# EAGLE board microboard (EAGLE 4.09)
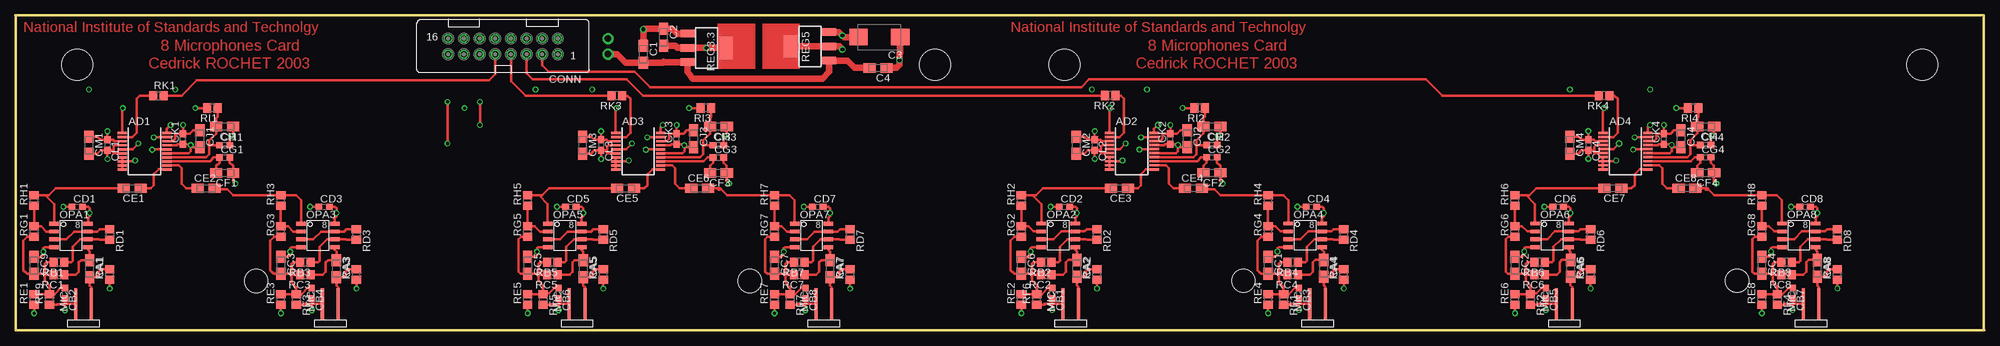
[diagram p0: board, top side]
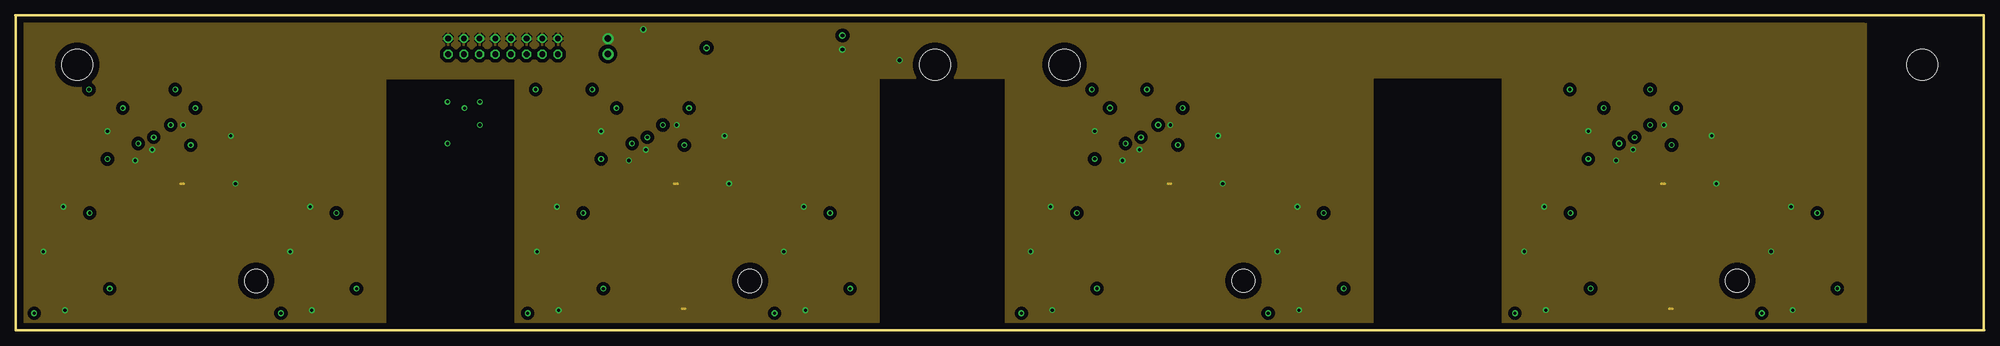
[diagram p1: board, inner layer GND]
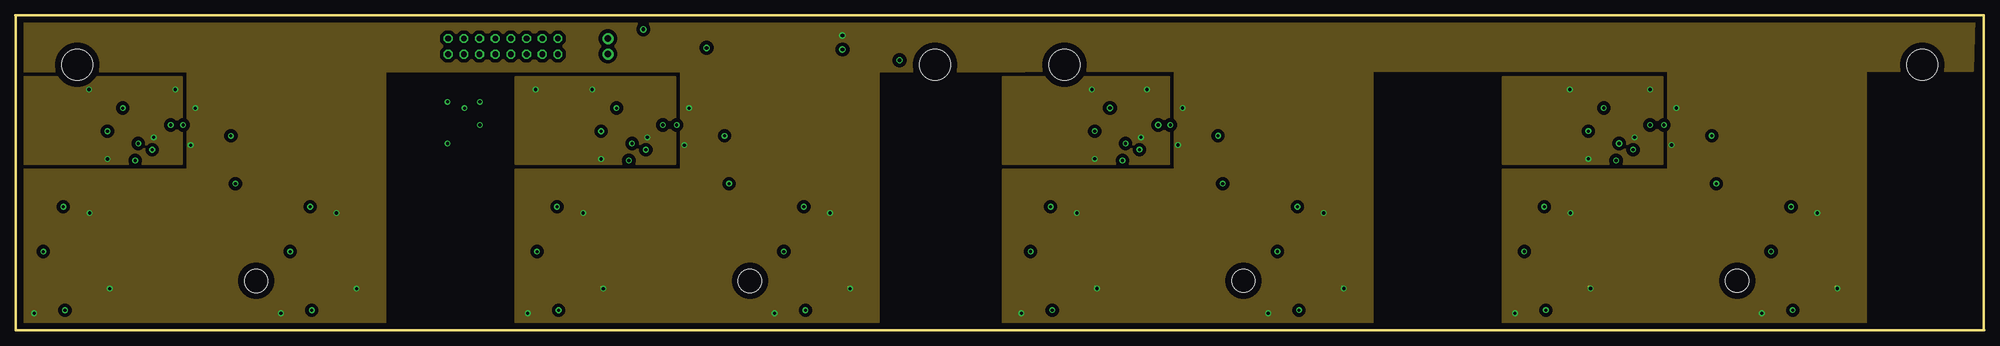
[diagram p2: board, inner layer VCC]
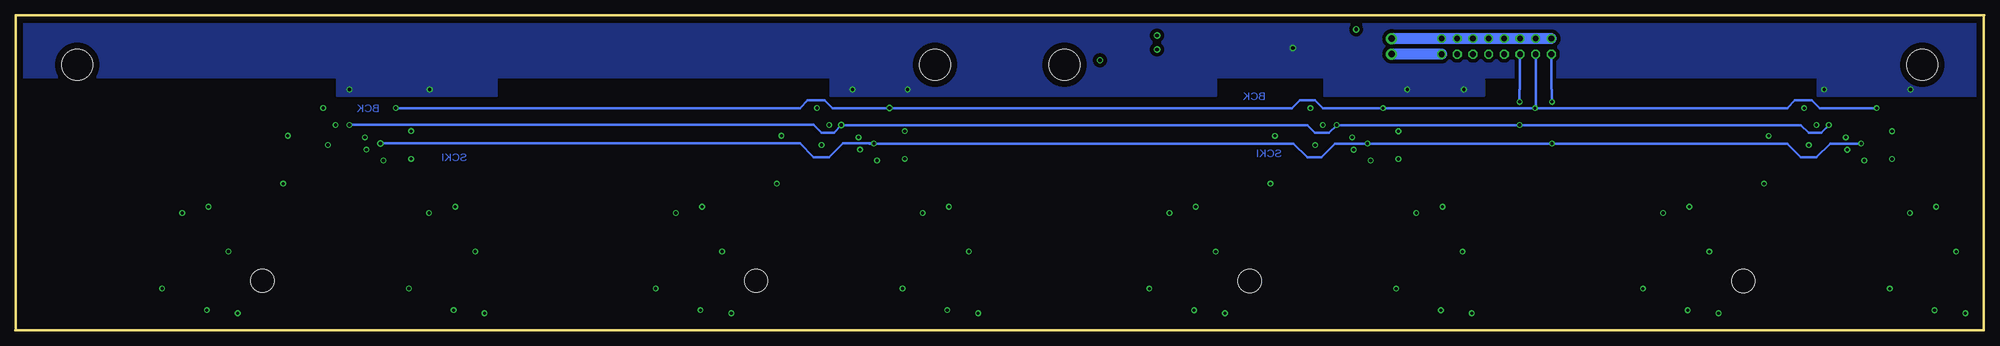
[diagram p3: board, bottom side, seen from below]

Size 319.04 x 51.01 mm. Coordinates in mm from the lower left corner, seen from the top.
Outline: 35.02,0 319.04,0
Outline: 0.02,51 0.02,0 35.02,0
Outline: 35.02,0 90.02,0
Outline: 35.02,0 60.02,0
Outline: 41.02,0 101.02,0
Outline: 319.02,0.01 319.02,51.01 0,51.01
Copper layers used: Top, GND, VCC, Bottom
Net classes: 0 default: width 0.305 mm, drill 0.203 mm, clearance 0.305 mm; 1 power: width 0.305 mm, drill 0.61 mm, clearance 0.61 mm
Holes 5.08 mm at 10.02,43 149.02,43 170.02,43.01 309.02,43.01
Holes 3.81 mm at 39.02,8 119.02,8 199.02,8.01 279.02,8.01

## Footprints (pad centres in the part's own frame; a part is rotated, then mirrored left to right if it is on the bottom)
SSOP20 = smd 0.4 x 1.5: 1 -2.925,-3.625; 2 -2.275,-3.625; 3 -1.625,-3.625; 4 -0.975,-3.625; 5 -0.325,-3.625; 6 0.325,-3.625; 7 0.975,-3.625; 8 1.625,-3.625; 9 2.275,-3.625; 10 2.925,-3.625; 11 2.925,3.625; 12 2.275,3.625; 13 1.625,3.625; 14 0.975,3.625; 15 0.325,3.625; 16 -0.325,3.625; 17 -0.975,3.625; 18 -1.625,3.625; 19 -2.275,3.625; 20 -2.925,3.625
A/3216-18R = smd 1.95 x 1.5: + 1.375,0; - -1.375,0
D/7343-31W = smd 2.95 x 2.7: + 3.375,0; - -3.375,0
C0603 = smd 1.1 x 1: 1 -0.85,0; 2 0.85,0
FE08-2 = drill 0.914 octagon: 1 -8.89,1.27; 2 -8.89,-1.27; 3 -6.35,1.27; 4 -6.35,-1.27; 5 -3.81,1.27; 6 -3.81,-1.27; 7 -1.27,1.27; 8 -1.27,-1.27; 9 1.27,1.27; 10 1.27,-1.27; 11 3.81,1.27; 12 3.81,-1.27; 13 6.35,1.27; 14 6.35,-1.27; 15 8.89,1.27; 16 8.89,-1.27
MIC = smd 0.5 x 5: P$2 1.27,1.27; P$4 -1.27,1.27
SO-08 = smd 0.61 x 1.524: 1 -1.27,-2.743; 2 0,-2.743; 3 1.27,-2.743; 4 2.54,-2.743; 5 2.54,2.743; 6 1.27,2.743; 7 0,2.743; 8 -1.27,2.743
R0805 = smd 1.3 x 1.5: 1 -0.85,0; 2 0.85,0
SOT223 = smd 1.219 x 2.235: 1 -2.311,-3.099; 2 0,-3.099; 3 2.311,-3.099 | smd 3.6 x 2.2: 4 0,3.099

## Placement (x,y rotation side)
AD1  PCM1802DB  [SSOP20]  20.91,29 270 top
AD2  PCM1802DB  [SSOP20]  180.91,29.01 270 top
AD3  PCM1802DB  [SSOP20]  100.91,29 270 top
AD4  PCM1802DB  [SSOP20]  260.91,29.01 270 top
C1  10uF  [A/3216-18R]  101.77,44.75 270 top
C2  10uF  [A/3216-18R]  105.02,47.5 270 top
C3  22uF  [D/7343-31W]  140.02,47.5 180 top
C4  0.47uF  [A/3216-18R]  139.77,42.5 180 top
CA1  1uF  [A/3216-18R]  12.02,10 270 top
CA2  1uF  [A/3216-18R]  172.02,10.01 270 top
CA3  1uF  [A/3216-18R]  52.02,10 270 top
CA4  1uF  [A/3216-18R]  212.02,10.01 270 top
CA5  1uF  [A/3216-18R]  92.02,10 270 top
CA6  1uF  [A/3216-18R]  252.02,10.01 270 top
CA7  1uF  [A/3216-18R]  132.02,10 270 top
CA8  1uF  [A/3216-18R]  292.02,10.01 270 top
CB1  0.1uF  [C0603]  168.02,6.01 270 top
CB2  0.1uF  [C0603]  8.02,6 270 top
CB3  0.1uF  [C0603]  208.02,6.01 270 top
CB4  0.1uF  [C0603]  48.02,6 270 top
CB5  0.1uF  [C0603]  248.02,6.01 270 top
CB6  0.1uF  [C0603]  88.02,6 270 top
CB7  0.1uF  [C0603]  288.02,6.01 270 top
CB8  0.1uF  [C0603]  128.02,6 270 top
CC1  10uF  [A/3216-18R]  203.02,10.51 270 top
CC2  10uF  [A/3216-18R]  243.02,10.51 270 top
CC3  10uF  [A/3216-18R]  43.02,10.5 270 top
CC4  10uF  [A/3216-18R]  283.02,10.51 270 top
CC5  10uF  [A/3216-18R]  83.02,10.5 270 top
CC6  10uF  [A/3216-18R]  163.02,10.51 270 top
CC7  10uF  [A/3216-18R]  123.02,10.5 270 top
CC9  10uF  [A/3216-18R]  3.02,10.5 270 top
CD1  0.1uF  [C0603]  10.02,20 0 top
CD2  0.1uF  [C0603]  170.02,20.01 0 top
CD3  0.1uF  [C0603]  50.02,20 0 top
CD4  0.1uF  [C0603]  210.02,20.01 0 top
CD5  0.1uF  [C0603]  90.02,20 0 top
CD6  0.1uF  [C0603]  250.02,20.01 0 top
CD7  0.1uF  [C0603]  130.02,20 0 top
CD8  0.1uF  [C0603]  290.02,20.01 0 top
CE1  1uF  [A/3216-18R]  18.91,23 180 top
CE2  1uF  [A/3216-18R]  30.91,23 0 top
CE3  1uF  [A/3216-18R]  178.91,23.01 180 top
CE4  1uF  [A/3216-18R]  190.91,23.01 0 top
CE5  1uF  [A/3216-18R]  98.91,23 180 top
CE6  1uF  [A/3216-18R]  110.91,23 0 top
CE7  1uF  [A/3216-18R]  258.91,23.01 180 top
CE8  1uF  [A/3216-18R]  270.91,23.01 0 top
CF1  4.7uF  [A/3216-18R]  33.91,25.5 180 top
CF2  4.7uF  [A/3216-18R]  193.91,25.51 180 top
CF3  4.7uF  [A/3216-18R]  113.91,25.5 180 top
CF4  4.7uF  [A/3216-18R]  273.91,25.51 180 top
CG1  0.1uF  [C0603]  33.91,28 0 top
CG2  0.1uF  [C0603]  193.91,28.01 0 top
CG3  0.1uF  [C0603]  113.91,28 0 top
CG4  0.1uF  [C0603]  273.91,28.01 0 top
CH1  0.1uF  [C0603]  33.91,30 0 top
CH2  0.1uF  [C0603]  193.91,30.01 0 top
CH3  0.1uF  [C0603]  113.91,30 0 top
CH4  0.1uF  [C0603]  273.91,30.01 0 top
CI1  4.7uF  [A/3216-18R]  33.91,33 180 top
CI2  4.7uF  [A/3216-18R]  193.91,33.01 180 top
CI3  4.7uF  [A/3216-18R]  113.91,33 180 top
CI4  4.7uF  [A/3216-18R]  273.91,33.01 180 top
CJ1  10uF  [A/3216-18R]  29.91,31 270 top
CJ2  10uF  [A/3216-18R]  189.91,31.01 270 top
CJ3  10uF  [A/3216-18R]  109.91,31 270 top
CJ4  10uF  [A/3216-18R]  269.91,31.01 270 top
CK1  0.1uF  [C0603]  27.16,31 90 top
CK2  0.1uF  [C0603]  187.16,31.01 90 top
CK3  0.1uF  [C0603]  107.16,31 90 top
CK4  0.1uF  [C0603]  267.16,31.01 90 top
CL1  0.1uF  [C0603]  14.91,30 270 top
CL2  0.1uF  [C0603]  174.91,30.01 270 top
CL3  0.1uF  [C0603]  94.91,30 270 top
CL4  0.1uF  [C0603]  254.91,30.01 270 top
CM1  10uF  [A/3216-18R]  11.91,30 270 top
CM2  10uF  [A/3216-18R]  171.91,30.01 270 top
CM3  10uF  [A/3216-18R]  91.91,30 270 top
CM4  10uF  [A/3216-18R]  251.91,30.01 270 top
CONN  [FE08-2]  79.02,46 180 top
MIC1  [MIC]  171.02,3.01 0 top
MIC2  [MIC]  11.02,3 0 top
MIC3  [MIC]  171.02,3 0 top
MIC4  [MIC]  51.02,3 0 top
MIC5  [MIC]  211.02,3.01 0 top
MIC6  [MIC]  91.02,3 0 top
MIC7  [MIC]  251.02,3.01 0 top
MIC8  [MIC]  131.02,3 0 top
MIC9  [MIC]  291.02,3.01 0 top
OPA1  OPA2228UA  [SO-08]  9.02,16 270 top
OPA2  OPA2228UA  [SO-08]  169.02,16.01 270 top
OPA3  OPA2228UA  [SO-08]  49.02,16 270 top
OPA4  OPA2228UA  [SO-08]  209.02,16.01 270 top
OPA5  OPA2228UA  [SO-08]  89.02,16 270 top
OPA6  OPA2228UA  [SO-08]  249.02,16.01 270 top
OPA7  OPA2228UA  [SO-08]  129.02,16 270 top
OPA8  OPA2228UA  [SO-08]  289.02,16.01 270 top
RA1  28k  [R0805]  15.27,9 90 top
RA2  28k  [R0805]  175.27,9.01 90 top
RA3  28k  [R0805]  55.27,9 90 top
RA4  28k  [R0805]  215.27,9.01 90 top
RA5  28k  [R0805]  95.27,9 90 top
RA6  28k  [R0805]  255.27,9.01 90 top
RA7  28k  [R0805]  135.27,9 90 top
RA8  28k  [R0805]  295.27,9.01 90 top
RB1  100  [R0805]  7.02,11 180 top
RB2  100  [R0805]  167.02,11.01 180 top
RB3  100  [R0805]  47.02,11 180 top
RB4  100  [R0805]  207.02,11.01 180 top
RB5  100  [R0805]  87.02,11 180 top
RB6  100  [R0805]  247.02,11.01 180 top
RB7  100  [R0805]  127.02,11 180 top
RB8  100  [R0805]  287.02,11.01 180 top
RC1  30K  [R0805]  7.02,9 180 top
RC2  30K  [R0805]  167.02,9.01 180 top
RC3  30K  [R0805]  47.02,9 180 top
RC4  30K  [R0805]  207.02,9.01 180 top
RC5  30K  [R0805]  87.02,9 180 top
RC6  30K  [R0805]  247.02,9.01 180 top
RC7  30K  [R0805]  127.02,9 180 top
RC8  30K  [R0805]  287.02,9.01 180 top
RD1  1K  [R0805]  15.27,15.5 270 top
RD2  1K  [R0805]  175.27,15.51 270 top
RD3  1k  [R0805]  55.27,15.5 270 top
RD4  1k  [R0805]  215.27,15.51 270 top
RD5  1k  [R0805]  95.27,15.5 270 top
RD6  1k  [R0805]  255.27,15.51 270 top
RD7  1k  [R0805]  135.27,15.5 270 top
RD8  1k  [R0805]  295.27,15.51 270 top
RE1  1k  [R0805]  3.02,5 90 top
RE2  1k  [R0805]  163.02,5.01 90 top
RE3  1k  [R0805]  43.02,5 90 top
RE4  1k  [R0805]  203.02,5.01 90 top
RE5  1k  [R0805]  83.02,5 90 top
RE6  1k  [R0805]  243.02,5.01 90 top
RE7  1k  [R0805]  123.02,5 90 top
RE8  1k  [R0805]  283.02,5.01 90 top
REG3.3  REG1117-3.3  [SOT223]  112.02,45.75 270 top
REG5  LM2940IMP  [SOT223]  128.77,46 90 top
RF1  1k  [R0805]  205.52,5.01 270 top
RF2  1k  [R0805]  245.52,5.01 270 top
RF3  1k  [R0805]  45.52,5 270 top
RF4  1k  [R0805]  285.52,5.01 270 top
RF5  1k  [R0805]  85.52,5 270 top
RF6  1k  [R0805]  165.52,5.01 90 top
RF7  1k  [R0805]  125.52,5 270 top
RF9  1k  [R0805]  5.52,5 90 top
RG1  1k  [R0805]  3.02,16 90 top
RG2  1k  [R0805]  163.02,16.01 90 top
RG3  1k  [R0805]  43.02,16 90 top
RG4  1k  [R0805]  203.02,16.01 90 top
RG5  1k  [R0805]  83.02,16 90 top
RG6  1k  [R0805]  243.02,16.01 90 top
RG7  1k  [R0805]  123.02,16 90 top
RG8  1k  [R0805]  283.02,16.01 90 top
RH1  6.8k  [R0805]  3.02,21 90 top
RH2  6.8k  [R0805]  163.02,21.01 90 top
RH3  6.8k  [R0805]  43.02,21 90 top
RH4  6.8k  [R0805]  203.02,21.01 90 top
RH5  6.8k  [R0805]  83.02,21 90 top
RH6  6.8k  [R0805]  243.02,21.01 90 top
RH7  6.8k  [R0805]  123.02,21 90 top
RH8  6.8k  [R0805]  283.02,21.01 90 top
RI1  1k  [R0805]  31.91,36 180 top
RI2  1k  [R0805]  191.91,36.01 180 top
RI3  1k  [R0805]  111.91,36 180 top
RI4  1k  [R0805]  271.91,36.01 180 top
RK1  100  [R0805]  23.16,38 0 top
RK2  100  [R0805]  177.45,38.03 180 top
RK3  100  [R0805]  97.45,38 180 top
RK4  100  [R0805]  257.45,38.01 180 top

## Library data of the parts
AD1-AD4 = microchip
C1-C4 CA1-CA8 CC1-CC7 CC9 CE1-CE8 CF1-CF4 CI1-CI4 CJ1-CJ4 CM1-CM4 RA1-RA8 RB1-RB8 RC1-RC8 RD1-RD8 RE1-RE8 RF1-RF7 RF9 RG1-RG8 RH1-RH8 RI1-RI4 RK1-RK4 = rcl
CB1-CB8 CD1-CD8 CG1-CG4 CH1-CH4 CK1-CK4 CL1-CL4 = smd-ipc
CONN = connecteur
MIC1-MIC9 = micro
OPA1-OPA8 = exar
REG3.3 REG5 = transistor-npn

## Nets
BCK [power]: AD1.1 AD2.1 AD3.1 AD4.1 CONN.13
GND [power]: AD1.3 AD1.7 AD1.8 AD1.9 AD1.10 AD1.16 AD1.18 AD2.3 AD2.7 AD2.8 AD2.9 AD2.10 AD2.16 AD2.18 AD3.3 AD3.7 AD3.8 AD3.9 AD3.10 AD3.16 AD3.18 AD4.3 AD4.7 AD4.8 AD4.9 AD4.10 AD4.16 AD4.18 C1.- C2.- C3.- C4.- CB1.2 CB2.2 CB3.2 CB4.2 CB5.2 CB6.2 CB7.2 CB8.2 CC1.- CC2.- CC3.- CC4.- CC5.- CC6.- CC7.- CC9.- CD1.1 CD2.1 CD3.1 CD4.1 CD5.1 CD6.1 CD7.1 CD8.1 CF1.- CF2.- CF3.- CF4.- CG1.2 CG2.2 CG3.2 CG4.2 CH1.2 CH2.2 CH3.2 CH4.2 CI1.- CI2.- CI3.- CI4.- CJ1.- CJ2.- CJ3.- CJ4.- CK1.2 CK2.2 CK3.2 CK4.2 CL1.1 CL2.1 CL3.1 CL4.1 CM1.- CM2.- CM3.- CM4.- CONN.2 CONN.4 CONN.6 CONN.8 CONN.10 CONN.12 CONN.14 CONN.16 MIC1.P$4 MIC2.P$4 MIC4.P$4 MIC5.P$4 MIC6.P$4 MIC7.P$4 MIC8.P$4 MIC9.P$4 OPA1.4 OPA2.4 OPA3.4 OPA4.4 OPA5.4 OPA6.4 OPA7.4 OPA8.4 REG3.3.1 REG5.2 REG5.4 RF1.2 RF2.2 RF3.2 RF4.2 RF5.2 RF6.1 RF7.2 RF9.1
LRCK [power]: AD1.20 AD2.20 AD3.20 AD4.20 CONN.11
S$1: OPA1.6 RB1.1 RD1.2
S$2: CA1.- OPA1.5 RC1.1
S$3: OPA3.6 RB3.1 RD3.2
S$5 [power]: MIC3.P$4
S$6: CA3.- OPA3.5 RC3.1
S$7: OPA1.3 OPA1.7 RD1.1
S$8: OPA3.3 OPA3.7 RD3.1
S$9: OPA3.2 RG3.2 RH3.1
S$10: CE2.+ OPA3.1 RH3.2
S$11: OPA2.6 RB2.1 RD2.2
S$12: CA2.- OPA2.5 RC2.1
S$13: OPA2.3 OPA2.7 RD2.1
S$14: OPA2.2 RG2.2 RH2.1
S$15: CE3.+ OPA2.1 RH2.2
S$16: AD2.12 CE4.-
S$17: AD2.11 CE3.-
S$18: AD2.13 CF2.+ CG2.1
S$20: AD2.14 CH2.1 CI2.+ RI2.1
S$21: AD2.2 RK2.1
S$24: OPA1.2 RG1.2 RH1.1
S$25: CE1.+ OPA1.1 RH1.2
S$26: CA2.+ MIC1.P$2 RA2.2
S$27: AD4.12
S$28: AD4.11
S$29: AD4.13 CG4.1
S$30: AD4.14 CH4.1 CI4.+ RI4.1
S$31: AD4.2 RK4.1
S$32: AD1.12 CE2.-
S$33: AD1.11 CE1.-
S$34: AD1.13 CF1.+ CG1.1
S$35: AD1.14 CH1.1 CI1.+ RI1.1
S$36: AD1.2 RK1.1
S$37: CONN.9 RK1.2
S$38: CA1.+ MIC2.P$2 RA1.2
S$42: CA3.+ MIC4.P$2 RA3.2
S$43: OPA5.6 RB5.1 RD5.2
S$44: CA5.- OPA5.5 RC5.1
S$45: OPA5.3 OPA5.7 RD5.1
S$46: OPA5.2 RG5.2 RH5.1
S$47: CE5.+ OPA5.1 RH5.2
S$48: CONN.5 RK2.2
S$49: OPA4.6 RB4.1 RD4.2
S$50: CA4.- OPA4.5 RC4.1
S$51: AD3.12
S$52: AD3.11
S$53: AD3.13 CG3.1
S$54: AD3.14 CH3.1 CI3.+ RI3.1
S$55: AD3.2 RK3.1
S$56: CONN.7 RK3.2
S$57: OPA4.3 OPA4.7 RD4.1
S$58: CE6.+ OPA7.1 RH7.2
S$59: OPA4.2 RG4.2 RH4.1
S$60: CE6.-
S$61: CE5.-
S$62: CF3.+
S$63: CA5.+ MIC6.P$2 RA5.2
S$64: OPA7.6 RB7.1 RD7.2
S$65: CA7.- OPA7.5 RC7.1
S$66: OPA7.3 OPA7.7 RD7.1
S$67: OPA7.2 RG7.2 RH7.1
S$68: CE4.+ OPA4.1 RH4.2
S$69: CA4.+ MIC5.P$2 RA4.2
S$70: OPA6.6 RB6.1 RD6.2
S$71: CA6.- OPA6.5 RC6.1
S$72: OPA6.3 OPA6.7 RD6.1
S$73: OPA6.2 RG6.2 RH6.1
S$74: CONN.3 RK4.2
S$75: CE7.+ OPA6.1 RH6.2
S$76: CE8.+ OPA8.1 RH8.2
S$77: CE8.-
S$78: CE7.-
S$79: CF4.+
S$80: CA6.+ MIC7.P$2 RA6.2
S$81: OPA8.6 RB8.1 RD8.2
S$83: CA8.- OPA8.5 RC8.1
S$84: CA7.+ MIC8.P$2 RA7.2
S$85: OPA8.3 OPA8.7 RD8.1
S$86: OPA8.2 RG8.2 RH8.1
S$87: CA8.+ MIC9.P$2 RA8.2
SCKI [power]: AD1.5 AD2.5 AD3.5 AD4.5 CONN.15
V_GND1: CB4.1 CC3.+ RB3.2 RC3.2 RE3.2 RF3.1 RG3.1
V_GND2: CB1.1 CC6.+ RB2.2 RC2.2 RE2.2 RF6.2 RG2.1
V_GND3: CB2.1 CC9.+ RB1.2 RC1.2 RE1.2 RF9.2 RG1.1
V_GND4: CB3.1 CC1.+ RB4.2 RC4.2 RE4.2 RF1.1 RG4.1
V_GND5: CB6.1 CC5.+ RB5.2 RC5.2 RE5.2 RF5.1 RG5.1
V_GND6: CB5.1 CC2.+ RB6.2 RC6.2 RE6.2 RF2.1 RG6.1
V_GND7: CB8.1 CC7.+ RB7.2 RC7.2 RE7.2 RF7.1 RG7.1
V_GND8: CB7.1 CC4.+ RB8.2 RC8.2 RE8.2 RF4.1 RG8.1
VCC [power]: AD1.15 AD1.17 AD2.15 AD2.17 AD3.15 AD3.17 AD4.15 AD4.17 C3.+ CD1.2 CD2.2 CD3.2 CD4.2 CD5.2 CD6.2 CD7.2 CD8.2 CJ1.+ CJ2.+ CJ3.+ CJ4.+ CK1.1 CK2.1 CK3.1 CK4.1 OPA1.8 OPA2.8 OPA3.8 OPA4.8 OPA5.8 OPA6.8 OPA7.8 OPA8.8 RA1.1 RA2.1 RA3.1 RA4.1 RA5.1 RA6.1 RA7.1 RA8.1 RE1.1 RE2.1 RE3.1 RE4.1 RE5.1 RE6.1 RE7.1 RE8.1 REG5.3 RI1.2 RI2.2 RI3.2 RI4.2
VCCINPUT [power]: C1.+ C4.+ CONN.1 REG3.3.3 REG5.1
VDD-3.3V [power]: AD1.4 AD1.6 AD1.19 AD2.4 AD2.6 AD2.19 AD3.4 AD3.6 AD3.19 AD4.4 AD4.6 AD4.19 C2.+ CL1.2 CL2.2 CL3.2 CL4.2 CM1.+ CM2.+ CM3.+ CM4.+ REG3.3.2 REG3.3.4

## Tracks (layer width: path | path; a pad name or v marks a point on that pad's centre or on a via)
BCK  (via drill 0.51, 0.61)
  Top 0.406: AD3.1 97.29,35.88 v97.41,36 | v17.41,36 17.29,35.88 AD1.1 | AD4.1 257.28,35.88 v257.41,36.01 | AD2.1 177.28,35.88 v177.41,36.01 v177.39,36.01 v177.39,36 | v177.39,36 v177.39,35.99 | v177.39,36 v177.38,36
  Bottom 0.406: CONN.13 72.67,36.1 v72.77,36 | v72.77,36 v97.41,36 107.16,36 108.41,37.25 110.91,37.25 112.16,36 v177.38,36 | 64.37,36 63.52,36 | v72.77,36 64.37,36 | 64.37,36 31.91,36 30.66,37.25 27.91,37.25 26.66,36 v17.41,36 | 223.52,36.01 224.37,36.01 | 224.37,36.01 v257.41,36.01 | 224.37,36.01 191.91,36.01 190.66,37.26 187.91,37.26 186.66,36.01 v177.41,36.01
GND  (via drill 0.51, 0.61, 1.02 pad 1.78)
  Top 0.406: OPA6.4 244.73,13.47 244.52,13.26 v244.52,12.76 244.52,12.26 244.14,11.88 CC2.- | MIC2.P$4 8.02,4.27 8.02,4.25 | 8.02,4.25 v8.02,3.25 | 8.02,4.25 CB2.2 | 8.02,4.25 6.77,4.25 6.77,4.15 RF9.1 | v247.77,20.01 CD6.1 | OPA1.4 4.73,13.46 4.52,13.25 v4.52,12.75 4.52,12.25 4.12,11.85 3.02,11.85 | 3.02,11.85 3.02,11.75 | CC9.- 3.02,11.85 | v7.77,20 CD1.1 | 254.91,31.01 v254.91,32.26 v254.91,32.27 | AD4.3 256.03,30.63 255.81,30.86 CL4.1 | v254.91,32.27 254.93,32.27 | CL4.1 v254.91,32.27 | CL4.1 253.81,30.86 253.28,31.38 CM4.- | AD4.8 AD4.7 | AD4.8 | v259.41,27.51 259.28,27.38 AD4.8 | AD4.8 257.28,27.88 | AD4.8 | 257.28,26.79 AD4.8 | 257.28,26.79 AD4.9 | 257.28,26.79 257.27,26.71 | AD4.10 257.28,26.79 | 288.02,4.26 v288.02,3.26 | 288.02,4.26 CB7.2 | 288.02,4.26 288,4.28 286.79,4.28 | 286.79,4.28 MIC9.P$4 | 286.79,4.28 286.67,4.16 RF4.2 | AD4.16 262.23,29.33 v262.16,29.26 262.26,29.36 | OPA8.4 284.73,13.47 284.52,13.26 v284.52,12.76 284.52,12.26 284.14,11.88 CC4.- | 17.29,26.61 17.29,26.62 | 17.29,26.61 17.27,26.61 | 17.29,26.61 AD1.10 | 17.29,27.88 17.3,27.88 | 17.29,27.88 AD1.7 | 17.29,26.61 AD1.9 AD1.8 | v19.41,27.5 19.29,27.38 AD1.8 | AD1.8 17.29,27.88 | AD1.3 16.04,30.62 15.81,30.85 CL1.1 | 14.91,31 v14.91,32.25 | 14.91,31 14.89,31 | CL1.1 14.91,31 | CL1.1 13.81,30.85 13.29,31.38 CM1.- | CJ4.- 268.78,32.38 268.26,31.86 CK4.2 | CK4.2 v267.16,33.26 | CK4.2 266.01,31.86 265.91,31.76 265.91,31.01 265.53,30.63 AD4.18 | CG4.2 274.76,27.16 275.28,26.63 CF4.- 275.28,24.13 v275.66,23.76 | 48.02,4.25 v48.02,3.25 | 48.02,4.25 CB4.2 | MIC4.P$4 46.79,4.27 46.77,4.25 | 46.77,4.25 48.02,4.25 | 46.77,4.25 46.67,4.15 RF3.2 | CI4.- 275.28,31.88 v274.91,31.51 274.76,31.36 CH4.2
  Top 0.406: AD1.16 22.24,29.32 v22.16,29.25 22.26,29.35 | OPA3.4 44.73,13.46 44.52,13.25 v44.52,12.75 44.52,12.25 44.15,11.88 CC3.- | CD8.1 v287.77,20.01 | CJ1.- 28.79,32.38 28.26,31.85 CK1.2 | CK1.2 v27.16,33.25 | CK1.2 26.01,31.85 25.91,31.75 25.91,31 25.54,30.62 AD1.18 | CG1.2 34.76,27.15 35.29,26.62 CF1.- 35.29,24.12 v35.66,23.75 | CI1.- 35.29,31.88 v34.91,31.5 34.76,31.35 CH1.2 | v47.77,20 CD3.1 | MIC6.P$4 88.04,4.27 88.02,4.25 | 88.02,4.25 CB6.2 | 88.02,4.25 v88.02,3.25 | 88.02,4.25 86.77,4.25 86.67,4.15 RF5.2 | OPA5.4 84.73,13.46 84.52,13.25 v84.52,12.75 84.52,12.25 84.15,11.88 CC5.- | v87.77,20 CD5.1 | 94.91,31 v94.91,32.25 v94.91,32.26 | AD3.3 96.04,30.62 95.81,30.85 CL3.1 | v94.91,32.26 94.93,32.26 | CL3.1 v94.91,32.26 | CL3.1 93.81,30.85 93.29,31.38 CM3.- | AD3.8 AD3.7 | AD3.8 | v99.41,27.5 99.29,27.38 AD3.8 | AD3.8 97.29,27.88 | AD3.8 | 97.29,26.78 AD3.8 | 97.29,26.78 AD3.9 | 97.29,26.78 97.28,26.7 | AD3.10 97.29,26.78 | 128.02,4.25 v128.02,3.25 | 128.02,4.25 CB8.2 | 128.02,4.25 128,4.27 126.79,4.27 | 126.79,4.27 MIC8.P$4 | 126.79,4.27 126.67,4.15 RF7.2 | AD3.16 102.24,29.32 v102.16,29.25 102.26,29.35 | OPA7.4 124.73,13.46 124.52,13.25 v124.52,12.75 124.52,12.25 124.15,11.88 CC7.- | CJ3.- 108.79,32.38 108.26,31.85 CK3.2 | CK3.2 v107.16,33.25 | CK3.2 106.01,31.85 105.91,31.75 105.91,31 105.54,30.62 AD3.18 | CG3.2 114.76,27.15 115.29,26.62 CF3.- 115.29,24.12 v115.66,23.75 | CI3.- 115.29,31.88 v114.91,31.5 114.76,31.35 CH3.2 | CD7.1 v127.77,20 | MIC1.P$4 168.02,4.28 168.02,4.26 | 168.02,4.26 v168.02,3.26 | 168.02,4.26 CB1.2 | 168.02,4.26 166.77,4.26 166.77,4.16 RF6.1 | OPA2.4 164.73,13.47 164.52,13.26 v164.52,12.76 164.52,12.26 164.12,11.86 163.02,11.86
  Top 0.406: 163.02,11.86 163.02,11.76 | CC6.- 163.02,11.86 | v167.77,20.01 CD2.1 | 177.28,26.62 177.28,26.63 | 177.28,26.62 177.27,26.62 | 177.28,26.62 AD2.10 | 177.28,27.89 177.3,27.89 | 177.28,27.89 AD2.7 | 177.28,26.62 AD2.9 AD2.8 | v179.41,27.51 179.28,27.38 AD2.8 | AD2.8 177.28,27.89 | AD2.3 176.03,30.63 175.81,30.86 CL2.1 | 174.91,31.01 v174.91,32.26 | 174.91,31.01 174.88,31.01 | CL2.1 174.91,31.01 | CL2.1 173.81,30.86 173.28,31.38 CM2.- | 208.02,4.26 v208.02,3.26 | 208.02,4.26 CB3.2 | MIC5.P$4 206.79,4.28 206.77,4.26 | 206.77,4.26 208.02,4.26 | 206.77,4.26 206.67,4.16 RF1.2 | AD2.16 182.23,29.33 v182.16,29.26 182.26,29.36 | OPA4.4 204.73,13.47 204.52,13.26 v204.52,12.76 204.52,12.26 204.14,11.88 CC1.- | CJ2.- 188.78,32.38 188.26,31.86 CK2.2 | CK2.2 v187.16,33.26 | CK2.2 186.01,31.86 185.91,31.76 185.91,31.01 185.53,30.63 AD2.18 | CG2.2 194.76,27.16 195.28,26.63 CF2.- 195.28,24.13 v195.66,23.76 | CI2.- 195.28,31.88 v194.91,31.51 194.76,31.36 CH2.2 | v207.77,20.01 CD4.1 | MIC7.P$4 248.04,4.28 248.02,4.26 | 248.02,4.26 CB5.2 | 248.02,4.26 v248.02,3.26 | 248.02,4.26 246.77,4.26 246.67,4.16 RF2.2
  Top 1.016: REG3.3.1 107.21,48.06 106.4,48.88 C2.- 101.9,48.88 v101.77,48.75 C1.- | C4.- 142.77,42.5 143.27,43 v143.27,43.75 143.27,44.75 143.4,44.88 C3.- | v134.02,45.5 133.52,46 REG5.2 REG5.4
  GND 0.406: v8.02,3.25 8.02,3.5 | v247.77,20.01 247.52,20.01 | 268.52,3.51 268.02,3.51 | 7.52,20 v7.77,20 | v288.02,3.26 288.02,3.51 | 266.77,23.76 267.27,23.76 | v48.02,3.25 48.02,3.5 | 26.77,23.75 27.27,23.75 | v287.77,20.01 287.52,20.01 | v47.77,20 47.52,20 | v88.02,3.25 88.02,3.5 | v87.77,20 87.52,20 | 108.52,3.5 108.02,3.5 | v128.02,3.25 128.02,3.5 | 106.77,23.75 107.27,23.75 | v127.77,20 127.52,20 | v168.02,3.26 168.02,3.51 | 167.52,20.01 v167.77,20.01 | v208.02,3.26 208.02,3.51 | 186.77,23.76 187.27,23.76 | v207.77,20.01 207.52,20.01 | v248.02,3.26 248.02,3.51
  Bottom 1.016: 96.02,47.27 v96.02,47.25 | 88.02,47.25 88.02,47.27 CONN.2 | 85.52,47.5 85.52,47.27 CONN.4 | 82.77,47.5 82.77,47.27 CONN.6 | 80.27,47.25 80.27,47.27 CONN.8 | 77.77,47.5 77.77,47.27 CONN.10 | 75.27,47.5 75.27,47.27 CONN.12 | 72.77,47.25 72.77,47.27 CONN.14
  Bottom 1.778: 96.02,47.27 CONN.2 CONN.4 CONN.6 | CONN.8 82.77,47.27 | 80.27,47.27 CONN.10 CONN.12 CONN.14 CONN.16
  pour GND: 0.02,50.5 299.49,50.75 299.49,41 0.02,40.75
  pour GND: 0.52,0.25 59.88,0.25 59.88,50.25 0.52,50.25
  pour GND: 81.02,0.25 139.88,0.25 139.88,50.25 81.02,50.25
  pour GND: 160.52,0.26 219.88,0.26 219.88,50.26 160.52,50.26
  pour GND: 241.02,0.26 299.88,0.26 299.88,50.26 241.02,50.26
LRCK  (via drill 0.51, 0.61)
  Top 0.406: AD3.20 104.54,32.88 v104.91,33.25 | v25.16,33.25 24.54,32.62 AD1.20 | v75.27,33.25 v75.27,37 | AD2.20 184.53,32.63 v185.16,33.26 | v264.91,33.26 264.53,32.88 AD4.20 | v185.16,33.26 v185.16,33.25 v185.21,33.25 | v185.16,33.26 185.16,33.27
  Bottom 0.406: 61.1,33.25 60.77,33.25 | 61.1,33.25 v75.27,33.25 v104.91,33.25 106.16,32 108.41,32 109.66,33.25 v185.21,33.25 185.44,33.02 | 61.1,33.25 29.66,33.25 28.41,32 26.41,32 v25.16,33.25 | CONN.11 75.21,39.06 75.27,39 v75.27,37 | v185.16,33.26 186.41,32.01 188.41,32.01 189.66,33.26 v264.9,33.26 v264.91,33.25 | v264.91,33.25 | v264.91,33.26 v264.91,33.25
S$1
  Top 0.406: RD1.2 13.67,14.65 13.5,14.73 OPA1.6 10.5,14.73 9.27,13.5 9.27,11.25 9.02,11 RB1.1
S$2
  Top 0.406: OPA1.5 11.77,13.01 12.02,12.75 CA1.- 10.65,11.38 10.27,11 10.27,9.5 9.77,9 RC1.1 7.77,9
S$3
  Top 0.406: RD3.2 53.67,14.65 53.5,14.73 OPA3.6 50.5,14.73 49.27,13.5 49.27,11.25 49.02,11 RB3.1
S$4  (via drill 0.51)
  other vias: 75.27,37
S$6
  Top 0.406: OPA3.5 51.77,13.01 52.02,12.75 CA3.- 50.65,11.38 50.27,11 50.27,9.5 49.77,9 RC3.1 47.77,9
S$7
  Top 0.406: OPA1.3 8.25,14.73 9.52,16 OPA1.7 13.27,16 13.62,16.35 RD1.1
S$8
  Top 0.406: OPA3.3 48.25,14.73 49.52,16 OPA3.7 53.27,16 53.62,16.35 RD3.1
S$9
  Top 0.406: OPA3.2 45.02,16 44.17,16.85 RG3.2 RH3.1 43.02,20.25
S$10
  Top 0.406: OPA3.1 46.28,21.05 45.48,21.85 RH3.2 35.32,21.85 34.31,22.86 32.3,22.86 CE2.+ | CE2.+ 32.3,23.01 | CE2.+
S$11
  Top 0.406: RD2.2 173.67,14.66 173.5,14.74 OPA2.6 170.5,14.74 169.27,13.51 169.27,11.26 169.02,11.01 RB2.1
S$12
  Top 0.406: OPA2.5 171.76,13.02 172.02,12.76 CA2.- 170.64,11.38 170.27,11.01 170.27,9.51 169.77,9.01 RC2.1 167.77,9.01
S$13
  Top 0.406: OPA2.3 168.25,14.74 169.52,16.01 OPA2.7 173.27,16.01 173.62,16.36 RD2.1
S$14
  Top 0.406: OPA2.2 165.02,16.01 164.17,16.86 RG2.2 RH2.1 163.02,20.26
S$15
  Top 0.406: OPA2.1 166.28,20.42 164.84,21.86 | 164.84,21.86 RH2.2 | CE3.+ 166.51,23.01 165.36,21.86 164.84,21.86
S$16
  Top 0.406: AD2.12 186.43,26.73 186.91,26.26 186.91,23.76 187.66,23.01 CE4.-
S$17
  Top 0.406: CE3.- 181.91,23.01 182.41,23.51 182.41,25.26 183.23,26.08 AD2.11
S$18
  Top 0.406: AD2.13 191.53,27.38 192.16,28.01 CG2.1 193.06,27.16 192.53,26.63 CF2.+
S$20
  Top 0.406: AD2.14 190.93,28.04 191.41,28.51 191.41,30.01 | 191.41,30.01 CH2.1 | 191.41,30.01 191.41,30.76 192.53,31.88 CI2.+ 192.53,34.38 192.76,34.61 RI2.1
S$21
  Top 0.406: RK2.1 179.16,38.03 179.66,37.53 179.66,32.03 179.65,32.03 | AD2.2 178.93,31.29 179.66,32.01 179.65,32.01 179.65,32.03 | 179.65,32.03 179.65,32.05
S$22  (via drill 0.51)
  other vias: 70.02,37
S$24
  Top 0.406: OPA1.2 5.02,16 4.17,16.85 RG1.2 RH1.1 3.02,20.25
S$25
  Top 0.406: OPA1.1 6.28,20.41 4.84,21.85 | 4.84,21.85 RH1.2 | CE1.+ 6.51,23 5.36,21.85 4.84,21.85
S$26
  Top 0.406: MIC1.P$2 172.29,6.99 172.02,7.26 CA2.+ 173.14,8.63 173.52,9.01 173.52,9.51 173.87,9.86 RA2.2
S$27
  Top 0.406: AD4.12 266.43,26.73 266.91,26.26
S$28
  Top 0.406: 263.23,26.08 AD4.11
S$29
  Top 0.406: AD4.13 271.53,27.38 272.16,28.01 CG4.1 273.06,27.16 272.53,26.63
S$30
  Top 0.406: AD4.14 270.93,28.04 271.41,28.51 271.41,30.01 | 271.41,30.01 CH4.1 | 271.41,30.01 271.41,30.76 272.53,31.88 CI4.+ 272.53,34.38 272.76,34.61 RI4.1
S$31
  Top 0.406: AD4.2 258.93,31.29 259.66,32.01 259.66,37.51 259.16,38.01 RK4.1
S$32
  Top 0.406: AD1.12 26.44,26.73 26.91,26.25 26.91,23.75 27.66,23 CE2.-
S$33
  Top 0.406: CE1.- 21.91,23 22.41,23.5 22.41,25.25 23.24,26.07 AD1.11
S$34
  Top 0.406: AD1.13 31.54,27.38 32.16,28 CG1.1 33.06,27.15 32.54,26.62 CF1.+
S$35
  Top 0.406: AD1.14 30.94,28.02 31.41,28.5 31.41,30 | 31.41,30 CH1.1 | 31.41,30 31.41,30.75 32.54,31.88 CI1.+ 32.54,34.38 32.76,34.6 RI1.1
S$36
  Top 0.406: AD1.2 18.94,31.27 19.66,32 19.66,37.5 20.16,38 RK1.1
S$37
  Top 0.406: CONN.9 77.75,41.48 76.77,40.5 29.41,40.5 26.91,38 RK1.2 23.91,38
S$38
  Top 0.406: MIC2.P$2 12.29,6.98 12.02,7.25 CA1.+ 13.15,8.62 13.52,9 13.52,9.5 13.87,9.85 RA1.2
S$42
  Top 0.406: MIC4.P$2 52.29,6.98 52.02,7.25 CA3.+ 53.15,8.62 53.52,9 53.52,9.5 53.87,9.85 RA3.2
S$43
  Top 0.406: RD5.2 93.67,14.65 93.5,14.73 OPA5.6 90.5,14.73 89.27,13.5 89.27,11.25 89.02,11 RB5.1
S$44
  Top 0.406: OPA5.5 91.77,13.01 92.02,12.75 CA5.- 90.65,11.38 90.27,11 90.27,9.5 89.77,9 RC5.1 87.77,9
S$45
  Top 0.406: OPA5.3 88.25,14.73 89.52,16 OPA5.7 93.27,16 93.62,16.35 RD5.1
S$46
  Top 0.406: OPA5.2 85.02,16 84.17,16.85 RG5.2 RH5.1 83.02,20.25
S$47
  Top 0.406: OPA5.1 86.28,20.42 84.85,21.85 | 84.85,21.85 RH5.2 | CE5.+ 86.52,23 85.37,21.85 84.85,21.85
S$48
  Top 0.406: 162.67,38.03 RK2.2 101.69,38.03 99.08,40.64 83.84,40.64 82.83,41.65 CONN.5
S$49
  Top 0.406: RD4.2 213.67,14.66 213.5,14.74 OPA4.6 210.5,14.74 209.27,13.51 209.27,11.26 209.02,11.01 RB4.1
S$50
  Top 0.406: OPA4.5 211.76,13.02 212.02,12.76 CA4.- 210.64,11.38 210.27,11.01 210.27,9.51 209.77,9.01 RC4.1 207.77,9.01
S$51
  Top 0.406: AD3.12 106.44,26.73 106.91,26.25
S$52
  Top 0.406: 103.24,26.07 AD3.11
S$53
  Top 0.406: AD3.13 111.54,27.38 112.16,28 CG3.1 113.06,27.15 112.54,26.62
S$54
  Top 0.406: AD3.14 110.94,28.02 111.41,28.5 111.41,30 | 111.41,30 CH3.1 | 111.41,30 111.41,30.75 112.54,31.88 CI3.+ 112.54,34.38 112.76,34.6 RI3.1
S$55
  Top 0.406: AD3.2 98.94,31.27 99.66,32 99.66,37.5 99.16,38 RK3.1
S$56
  Top 0.406: CONN.7 80.29,40.38 82.67,38 RK3.2
S$57
  Top 0.406: OPA4.3 208.25,14.74 209.52,16.01 OPA4.7 213.27,16.01 213.62,16.36 RD4.1
S$58
  Top 0.406: OPA7.1 126.28,21.06 125.49,21.85 RH7.2 115.33,21.85 114.32,22.86 | 114.32,22.86 114.21,22.75 113.91,22.75 | CE6.+ 114.18,23 114.32,22.86
S$59
  Top 0.406: OPA4.2 205.02,16.01 204.17,16.86 RG4.2 RH4.1 203.02,20.26
S$60
  Top 0.406: CE6.- 107.66,23 106.91,23.75 106.91,26.25
S$61
  Top 0.406: CE5.- 101.91,23 102.41,23.5 102.41,25.25 103.24,26.07
S$62
  Top 0.406: CF3.+ 112.54,26.62
S$63
  Top 0.406: MIC6.P$2 92.29,6.98 92.02,7.25 CA5.+ 93.15,8.62 93.52,9 93.52,9.5 93.87,9.85 RA5.2
S$64
  Top 0.406: RD7.2 133.67,14.65 133.5,14.73 OPA7.6 130.5,14.73 129.27,13.5 129.27,11.25 129.02,11 RB7.1
S$65
  Top 0.406: OPA7.5 131.77,13.01 132.02,12.75 CA7.- 130.65,11.38 130.27,11 130.27,9.5 129.77,9 RC7.1 127.77,9
S$66
  Top 0.406: OPA7.3 128.25,14.73 129.52,16 OPA7.7 133.27,16 133.62,16.35 RD7.1
S$67
  Top 0.406: OPA7.2 125.02,16 124.17,16.85 RG7.2 RH7.1 123.02,20.25
S$68
  Top 0.406: OPA4.1 206.28,21.06 205.48,21.86 RH4.2 195.32,21.86 194.31,22.87 192.28,22.87 192.32,22.87 | 192.32,22.87 192.32,23.01 CE4.+ | 192.32,22.87
S$69
  Top 0.406: MIC5.P$2 212.29,6.99 212.02,7.26 CA4.+ 213.14,8.63 213.52,9.01 213.52,9.51 213.87,9.86 RA4.2
S$70
  Top 0.406: RD6.2 253.67,14.66 253.5,14.74 OPA6.6 250.5,14.74 249.27,13.51 249.27,11.26 249.02,11.01 RB6.1
S$71
  Top 0.406: OPA6.5 251.76,13.02 252.02,12.76 CA6.- 250.64,11.38 250.27,11.01 250.27,9.51 249.77,9.01 RC6.1 247.77,9.01
S$72
  Top 0.406: OPA6.3 248.25,14.74 249.52,16.01 OPA6.7 253.27,16.01 253.62,16.36 RD6.1
S$73
  Top 0.406: OPA6.2 245.02,16.01 244.17,16.86 RG6.2 RH6.1 243.02,20.26
S$74
  Top 0.406: 242.67,38.01 RK4.2 231.25,38.01 228.62,40.64 174.01,40.64 172.74,39.37 102.89,39.37 100.35,41.91 86.38,41.91 85.37,42.92 CONN.3
S$75
  Top 0.406: OPA6.1 246.28,20.43 244.85,21.86 | 244.85,21.86 RH6.2 | CE7.+ 246.52,23.01 245.37,21.86 244.85,21.86
S$76
  Top 0.406: OPA8.1 286.28,21.07 285.49,21.86 RH8.2 275.33,21.86 274.32,22.87 | 274.32,22.87 274.21,22.76 273.91,22.76 | CE8.+ 274.18,23.01 274.32,22.87
S$77
  Top 0.406: CE8.- 267.66,23.01 266.91,23.76 266.91,26.26
S$78
  Top 0.406: CE7.- 261.91,23.01 262.41,23.51 262.41,25.26 263.23,26.08
S$79
  Top 0.406: CF4.+ 272.53,26.63
S$80
  Top 0.406: MIC7.P$2 252.29,6.99 252.02,7.26 CA6.+ 253.14,8.63 253.52,9.01 253.52,9.51 253.87,9.86 RA6.2
S$81
  Top 0.406: RD8.2 293.67,14.66 293.5,14.74 OPA8.6 290.5,14.74 289.27,13.51 289.27,11.26 289.02,11.01 RB8.1
S$83
  Top 0.406: OPA8.5 291.76,13.02 292.02,12.76 CA8.- 290.64,11.38 290.27,11.01 290.27,9.51 289.77,9.01 RC8.1 287.77,9.01
S$84
  Top 0.406: MIC8.P$2 132.29,6.98 132.02,7.25 CA7.+ 133.15,8.62 133.52,9 133.52,9.5 133.87,9.85 RA7.2
S$85
  Top 0.406: OPA8.3 288.25,14.74 289.52,16.01 OPA8.7 293.27,16.01 293.62,16.36 RD8.1
S$86
  Top 0.406: OPA8.2 285.02,16.01 284.17,16.86 RG8.2 RH8.1 283.02,20.26
S$87
  Top 0.406: MIC9.P$2 292.29,6.99 292.02,7.26 CA8.+ 293.14,8.63 293.52,9.01 293.52,9.51 293.87,9.86 RA8.2
SCKI  (via drill 0.51, 0.61)
  Top 0.406: AD1.5 18.99,29.32 v19.91,30.25 | AD3.5 98.99,29.32 v99.91,30.25 | v70.02,30.25 v70.02,37 | v179.91,30.26 178.98,29.33 AD2.5 | AD4.5 258.98,29.33 v259.91,30.26 v259.92,30.26 | v259.92,30.26 v259.91,30.26 | v259.92,30.26
  Bottom 0.406: v70.02,37 70.02,39 70.13,39.11 CONN.15 | 63.64,30.25 63.02,30.25 | 63.64,30.25 v70.02,30.25 v99.91,30.25 105.16,30.25 107.41,28 109.66,28 111.91,30.25 180.65,30.25 180.65,30.26 v179.91,30.26 184.91,30.26 187.16,28.01 189.66,28.01 191.91,30.26 v259.91,30.26 | 63.64,30.25 31.91,30.25 29.66,28 27.16,28 24.91,30.25 v19.91,30.25
V_GND1
  Top 0.406: RG3.1 41.92,15.15 41.27,14.5 41.27,9.75 41.52,9.5 | 41.52,9.5 41.77,9.25 | 41.52,9.5 41.9,9.12 CC3.+ 44.65,9.12 | RB3.2 45.02,11 44.77,10.75 44.77,9.25 | 44.77,9 44.77,7.75 45.52,7 RF3.1 | RF3.1 45.52,5.75 | RE3.2 43.02,6 43.17,5.85 RF3.1 | CB4.1 47.37,6.85 46.37,5.85 RF3.1 | 44.77,9 RC3.2 | 44.77,9 44.65,9.12 | 44.77,9 44.77,9.25 | 44.65,9.12 44.77,9.25
V_GND2
  Top 0.406: CB1.1 167.37,6.86 166.37,5.86 RF6.2 | RE2.2 163.02,5.76 163.12,5.86 RF6.2 | RF6.2 165.52,7.26 164.77,8.01 164.77,9.01 | RB2.2 165.02,11.01 164.77,10.76 164.77,9.26 | 164.77,9.01 RC2.2 | 164.64,9.13 CC6.+ 161.89,9.13 161.27,9.76 161.27,14.51 161.92,15.16 RG2.1 | 164.64,9.13 164.77,9.26 | 164.77,9.01 164.64,9.13 | 164.77,9.01 164.77,9.26
V_GND3
  Top 0.406: CB2.1 7.37,6.85 6.37,5.85 RF9.2 | RE1.2 3.02,5.75 3.12,5.85 RF9.2 | RF9.2 5.52,7.25 4.77,8 4.77,9 | RB1.2 5.02,11 4.77,10.75 4.77,9.25 | 4.77,9 RC1.2 | 4.65,9.12 CC9.+ 1.9,9.12 1.27,9.75 1.27,14.5 1.92,15.15 RG1.1 | 4.65,9.12 4.77,9.25 | 4.77,9 4.65,9.12 | 4.77,9 4.77,9.25
V_GND4
  Top 0.406: RG4.1 201.92,15.16 201.27,14.51 201.27,9.76 201.52,9.51 | 201.52,9.51 201.77,9.26 | 201.52,9.51 201.89,9.13 CC1.+ 204.64,9.13 | RB4.2 205.02,11.01 204.77,10.76 204.77,9.26 | 204.77,9.01 204.77,7.76 205.52,7.01 RF1.1 | RF1.1 205.52,5.76 | RE4.2 203.02,6.01 203.17,5.86 RF1.1 | CB3.1 207.37,6.86 206.37,5.86 RF1.1 | 204.77,9.01 RC4.2 | 204.77,9.01 204.64,9.13 | 204.77,9.01 204.77,9.26 | 204.64,9.13 204.77,9.26
V_GND5
  Top 0.406: RG5.1 81.92,15.15 81.52,14.75 81.52,9.5 81.9,9.12 CC5.+ 84.65,9.12 84.77,9 | RB5.2 85.02,11 84.77,10.75 84.77,9 | 84.77,9 84.77,8 85.52,7.25 RF5.1 | RE5.2 RF5.1 | RF5.1 85.62,5.85 85.77,6 86.52,6 87.37,6.85 CB6.1 | 84.77,9 RC5.2
V_GND6
  Top 0.406: RG6.1 241.92,15.16 241.52,14.76 241.52,9.51 241.89,9.13 CC2.+ 244.64,9.13 244.77,9.01 | RB6.2 245.02,11.01 244.77,10.76 244.77,9.01 | 244.77,9.01 244.77,8.01 245.52,7.26 RF2.1 | RF2.1 RE6.2 | RF2.1 245.62,5.86 245.77,6.01 246.52,6.01 247.37,6.86 CB5.1 | 244.77,9.01 RC6.2
V_GND7
  Top 0.406: CB8.1 127.37,6.85 126.37,5.85 RF7.1 | RE7.2 123.02,5.75 123.12,5.85 RF7.1 | RB7.2 125.02,11 124.77,10.75 124.77,9.25 124.77,9 | 124.77,9 124.77,7.75 125.52,7 RF7.1 | 124.77,9 RC7.2 | 124.77,9 124.65,9.12 CC7.+ 121.9,9.12 121.52,9.5 121.52,14.75 121.92,15.15 RG7.1 | RF7.1 125.52,5.75
V_GND8
  Top 0.406: CB7.1 287.37,6.86 286.37,5.86 RF4.1 | RE8.2 283.02,5.76 283.12,5.86 RF4.1 | RB8.2 285.02,11.01 284.77,10.76 284.77,9.26 284.77,9.01 | 284.77,9.01 284.77,7.76 285.52,7.01 RF4.1 | 284.77,9.01 RC8.2 | 284.77,9.01 284.64,9.13 CC4.+ 281.89,9.13 281.52,9.51 281.52,14.76 281.92,15.16 RG8.1 | RF4.1 285.52,5.76
VCC  (via drill 0.51, 0.61)
  Top 0.406: RE1.1 v3.02,2.75 | v255.27,6.76 RA6.1 | CD6.2 251.77,20.01 252.02,19.76 v252.02,19.01 252.02,18.51 251.76,18.25 OPA6.8 | v15.27,6.75 RA1.1 | CD1.2 11.77,20 12.02,19.75 v12.02,19 12.02,18.5 11.77,18.24 OPA1.8 | RE8.1 v283.02,2.76 | AD4.17 266.13,29.98 266.31,30.16 CK4.1 268.26,30.16 v268.41,30.01 | CJ4.+ 268.78,29.63 v268.41,30.01 | v268.41,30.01 268.41,29.01 268.08,28.68 AD4.15 | RE3.1 v43.02,2.75 | v295.27,6.76 RA8.1 | v269.16,36.01 RI4.2 | CD8.2 291.77,20.01 292.02,19.76 v292.02,19.01 292.02,18.51 291.76,18.25 OPA8.8 | AD1.17 26.14,29.98 26.31,30.15 CK1.1 28.26,30.15 v28.41,30 | CJ1.+ 28.79,29.62 v28.41,30 | v28.41,30 28.41,29 28.09,28.68 AD1.15 | v55.27,6.75 RA3.1 | v29.16,36 RI1.2 | CD3.2 51.77,20 52.02,19.75 v52.02,19 52.02,18.5 51.77,18.24 OPA3.8 | RE5.1 v83.02,2.75 | v95.27,6.75 RA5.1 | CD5.2 91.77,20 92.02,19.75 v92.02,19 92.02,18.5 91.77,18.24 OPA5.8 | RE7.1 v123.02,2.75 | AD3.17 106.14,29.98 106.31,30.15 CK3.1 108.26,30.15 v108.41,30 | CJ3.+ 108.79,29.62 v108.41,30 | v108.41,30 108.41,29 108.09,28.68 AD3.15 | v135.27,6.75 RA7.1 | v109.16,36 RI3.2 | CD7.2 131.77,20 132.02,19.75 v132.02,19 132.02,18.5 131.77,18.24 OPA7.8 | RE2.1 v163.02,2.76 | 134.27,47.5 134.27,47.7 134.02,47.7 v134.02,47.75 | v175.27,6.76 RA2.1 | CD2.2 171.77,20.01 172.02,19.76 v172.02,19.01 172.02,18.51 171.76,18.25 OPA2.8 | RE4.1 v203.02,2.76 | AD2.17 186.13,29.98 186.31,30.16 CK2.1 188.26,30.16 v188.41,30.01 | CJ2.+ 188.78,29.63 v188.41,30.01 | v188.41,30.01 188.41,29.01 188.08,28.68 AD2.15 | v215.27,6.76 RA4.1 | v189.16,36.01 RI2.2 | CD4.2 211.77,20.01 212.02,19.76 v212.02,19.01 212.02,18.51 211.76,18.25 OPA4.8
  Top 0.406: RE6.1 v243.02,2.76
  Top 1.016: C3.+ 134.27,47.5 v134.02,47.75 133.46,48.31 REG5.3
  VCC 0.406: v3.02,2.75 3.02,3 | v255.27,6.76 255.02,7.01 | 15.02,7 v15.27,6.75 | v283.02,2.76 283.02,3.01 | v43.02,2.75 43.02,3 | v295.27,6.76 295.02,7.01 | v55.27,6.75 55.02,7 | v83.02,2.75 83.02,3 | v95.27,6.75 95.02,7 | v123.02,2.75 123.02,3 | v135.27,6.75 135.02,7 | v163.02,2.76 163.02,3.01 | v175.27,6.76 175.02,7.01 | v203.02,2.76 203.02,3.01 | v215.27,6.76 215.02,7.01 | v243.02,2.76 243.02,3.01
  pour VCC: 0.02,0 59.88,0 59.88,42 163.56,42 163.81,50.5 0.27,50.5 0.02,42 27.91,42 27.91,26 0.02,26
  pour VCC: 81.02,0 139.88,0 139.88,43 107.91,44.27 107.91,26 81.02,26
  pour VCC: 160.02,0.01 219.88,0.01 219.88,42.01 317.21,42.01 317.46,50.51 138.68,50.51 138.43,42.01 187.91,42.01 187.91,26.01 160.02,26.01
  pour VCC: 241.02,0.01 299.88,0.01 299.88,43.01 267.91,44.28 267.91,26.01 241.02,26.01
VCCINPUT  (via drill 1.02 pad 1.78)
  Top 1.016: v96.02,44.75 97.52,44.75 98.9,43.38 C1.+ 104.9,43.38 105.02,43.5 105.08,43.44 REG3.3.3 108.92,41.85 109.77,40.75 130.77,40.75 131.87,41.85 REG5.1 134.83,43.69 136.02,42.5 C4.+
  Top 1.778: v96.02,44.75 96,44.73
  Bottom 1.778: CONN.1 96,44.73 v96.02,44.75
VDD-3.3V  (via drill 0.51, 0.61)
  Top 0.406: AD4.4 256.13,29.98 255.91,29.76 255.91,29.01 | AD4.6 255.98,28.68 255.91,28.76 255.91,29.01 | 254.91,29.25 254.91,29.26 | 254.91,29.25 254.93,29.25 | 255.91,29.01 255.81,29.16 CL4.2 | CL4.2 v254.91,27.76 | CL4.2 254.91,29.25 | CL4.2 253.81,29.16 253.28,28.63 CM4.+ | AD4.19 262.43,31.29 v262.41,31.26 | AD1.4 16.14,29.98 15.91,29.75 15.91,29 | AD1.6 15.99,28.68 15.91,28.75 15.91,29 | 14.91,29.11 CL1.2 | 15.91,29 15.81,29.15 CL1.2 | CL1.2 v14.91,27.75 | CL1.2 14.91,29.25 | CL1.2 13.81,29.15 13.29,28.62 CM1.+ | AD1.19 22.44,31.27 v22.41,31.25 | AD3.4 96.14,29.98 95.91,29.75 95.91,29 | AD3.6 95.99,28.68 95.91,28.75 95.91,29 | 94.91,29.24 94.91,29.25 | 94.91,29.24 94.93,29.24 | 95.91,29 95.81,29.15 CL3.2 | CL3.2 v94.91,27.75 | CL3.2 94.91,29.24 | CL3.2 93.81,29.15 93.29,28.62 CM3.+ | AD3.19 102.44,31.27 v102.41,31.25 | AD2.4 176.13,29.98 175.91,29.76 175.91,29.01 | AD2.6 175.98,28.68 175.91,28.76 175.91,29.01 | 174.9,29.12 174.91,29.12 CL2.2 | 175.91,29.01 175.81,29.16 CL2.2 | CL2.2 v174.91,27.76 | CL2.2 174.91,29.26 | CL2.2 173.81,29.16 173.28,28.63 CM2.+ | AD2.19 182.43,31.29 v182.41,31.26
  Top 1.016: REG3.3.4 v112.02,45.75 REG3.3.2 107.27,45.75 106.9,46.12 C2.+
  VCC 0.406: v262.41,31.26 262.16,31.26 | v22.41,31.25 22.16,31.25 | v102.41,31.25 102.16,31.25 | v182.41,31.26 182.16,31.26
  other vias: 251.91,39.01 264.91,39.01 11.91,39 25.91,39 84.29,39 93.48,39 174.45,39.01 183.37,39.01
  pour Bottom: 0.02,51 175.03,51 175.03,41 106.91,41 106.91,38 81.02,38 81.02,41 26.91,41 26.91,38 0.02,38
  pour VCC: 0.02,41 26.91,41 26.91,27 0.02,27
  pour VCC: 81.02,41 106.91,41 106.91,27 81.02,27
  pour Bottom: 124.46,51.01 318.52,51.01 318.52,41.01 266.91,41.01 266.91,38.01 241.02,38.01 241.02,41.01 186.91,41.01 186.91,38.01 124.46,38.01
  pour VCC: 160.02,41.01 186.91,41.01 186.91,27.01 160.02,27.01
  pour VCC: 241.02,41.01 266.91,41.01 266.91,27.01 241.02,27.01
(copper drawn outside any net)
  shapes: Top area x3

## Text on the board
Top: National Institute of Standards and Technolgy | National Institute of Standards and Technolgy | 8 Microphones Card | 8 Microphones Card | Cedrick ROCHET 2003 | Cedrick ROCHET 2003
Bottom: BCK | BCK | SCKI | SCKI
tValues: National Institute of Standards and Technolgy | National Institute of Standards and Technolgy | 8 Microphones Card | 8 Microphones Card | Cedrick ROCHET 2003 | Cedrick ROCHET 2003 | SCKI | LRCK | BCK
